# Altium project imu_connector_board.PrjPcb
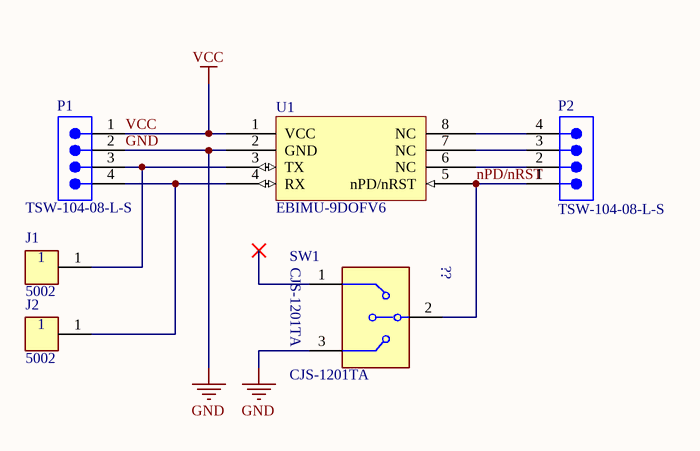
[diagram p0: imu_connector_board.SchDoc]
1 sheet, 6 parts. Net scope: global (net labels, ports and power ports of the same name join across sheets).
Board file: imu_connector_board.PcbDoc

## Sheet imu_connector_board.SchDoc
size A4; SheetNumber: 1; SheetTotal: 1

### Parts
J1  5002  [FP-5002-MFG]
J2  5002  [FP-5002-MFG]
P1  TSW-104-08-L-S  [SMTC-TSW-104-08-X-S]
P2  TSW-104-08-L-S  [SMTC-TSW-104-08-X-S]
SW1  CJS-1201TA  [FP-CJS-1201TA-MFG]
U1  EBIMU-9DOFV6  [EBIMU-9DOFV6]

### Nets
GND: P1.2 SW1.3 U1.2(GND)
VCC: P1.1 U1.1(VCC)
nPD/nRST: P2.1 SW1.2(C) U1.5(nPD/nRST)
NetJ1_1: J1.1 P1.3 U1.3(TX)
NetJ2_1: J2.1 P1.4 U1.4(RX)
NetP2_2: P2.2 U1.6(NC)
NetP2_3: P2.3 U1.7(NC)
NetP2_4: P2.4 U1.8(NC)

Not connected (* = marked no-connect by the designer): SW1 1*

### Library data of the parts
J1 J2 = CMP-2000-05182-2: PC TEST POINT MINIATURE WHITE; Body Material: Bronze; Insulation: Insulated; Inside Diameter: 1.27mm; Number of Ports: 1; Outside Diameter: 2.54mm; Hole Diameter: 1.6mm; Plating: Silver
P1 P2 = CMP-1024-00358-1: 0.025" SQ Post Header, Through-hole, Vertical, -55 to 125 degC, 2.54 mm Pitch, 4-Pin, Male, RoHS; Manufacturer: Samtec; Pitch: 2.54 mm
SW1 = CMP-71745-000001-1: SWITCH SLIDE SPDT 100MA 6V; Manufacturer: Copal Electronics Inc; Standoff Height: 0mm; Operating Force: 5.9N; Contact Resistance: 100mΩ
U1 = CMP-00000-2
